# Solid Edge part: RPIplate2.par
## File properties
Author: wojci
Template: ISO Metric Part.par
Last saved by: wojci
Revision: 7
Application: Solid Edge
Username: wojci
Accuracy: 0.990
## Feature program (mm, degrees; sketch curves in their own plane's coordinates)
sketch for "unnamed Protrusion 1" plane through (0, 0, 0) normal (0, 0, 1) x-axis (1, 0, 0)
  line (29, -49) -> (-29, -49)
  line (-29, -49) -> (-29, 47)
  line (-29, 47) -> (29, 47)
  line (29, 47) -> (29, -49)
extrude "unnamed Protrusion 1" add finite 3 along +normal
sketch for "ExtrudedProtrusion_2" plane through (0, -1, 0) normal (0, 0, -1) x-axis (1, 0, 0)
  line (-26, -17) -> (-26, 42)
  line (-26, 42) -> (42, 42)
  line (42, 42) -> (42, -17)
  line (42, -17) -> (-26, -17)
extrude "ExtrudedProtrusion_2" add finite 3 along -normal
sketch for "ExtrudedProtrusion_3" #1 plane through (-3, -1, 3) normal (0, 0, 1) x-axis (0, 1, 0)
  line (-38.5, -41.5) -> (-38.5, 19.5)
  line (-38.5, 19.5) -> (13.5, 19.5)
  line (13.5, 19.5) -> (13.5, -41.5)
  line (13.5, -41.5) -> (-38.5, -41.5)
sketch for "ExtrudedProtrusion_3" #2 plane through (-3, -1, 3) normal (0, 0, 1) x-axis (0, 1, 0)
  line (-35.5, -38.5) -> (-35.5, 16.5)
  line (-35.5, 16.5) -> (10.5, 16.5)
  line (10.5, 16.5) -> (10.5, -38.5)
  line (10.5, -38.5) -> (-35.5, -38.5)
extrude "ExtrudedProtrusion_3" add finite 11 along +normal
sketch for "ExtrudedProtrusion_4" #1 plane through (3, -9.5, 3) normal (0, 0, 1) x-axis (-1, 0, 0)
  circle centre (-34, 28.5) radius 4
sketch for "ExtrudedProtrusion_4" #2 plane through (3, -9.5, 3) normal (0, 0, 1) x-axis (-1, 0, 0)
  circle centre (-34, -20.5) radius 4
sketch for "ExtrudedProtrusion_4" #3 plane through (3, -9.5, 3) normal (0, 0, 1) x-axis (-1, 0, 0)
  circle centre (24, -20.5) radius 4
sketch for "ExtrudedProtrusion_4" #4 plane through (3, -9.5, 3) normal (0, 0, 1) x-axis (-1, 0, 0)
  circle centre (24, 28.5) radius 4
extrude "ExtrudedProtrusion_4" add finite 14 along +normal
sketch for "Hole_1" plane through (4.75, -1, 3) normal (0, 0, 1) x-axis (-1, 0, 0)
hole "Hole_1" diameter 3.6 through
sketch for "unnamed Hole 1" plane through (4.75, -1, 3) normal (0, 0, 1) x-axis (-1, 0, 0)
  hole centre (21.75, -41) bore radius 1.8
hole "unnamed Hole 1" through
sketch for "unnamed Hole 2" plane through (4.75, -1, 3) normal (0, 0, 1) x-axis (-1, 0, 0)
  hole centre (4.75, -1) bore radius 1.8
hole "unnamed Hole 2" through
sketch for "unnamed Hole 3" plane through (4.75, -1, 3) normal (0, 0, 1) x-axis (-1, 0, 0)
  hole centre (-2.25, 47) bore radius 1.8
hole "unnamed Hole 3" through
sketch for "unnamed Hole 4" plane through (4.75, -1, 3) normal (0, 0, 1) x-axis (-1, 0, 0)
  hole centre (11.75, 47) bore radius 1.8
hole "unnamed Hole 4" through
sketch for "Hole_6" plane through (-26, 15, 17) normal (0, 0, 1) x-axis (1, 0, 0)
  hole centre (5, -4) bore radius 1.0065
hole "Hole_6" nominal diameter 2.5 through  ThreadDepth = 6.2 mm
sketch for "unnamed Hole 5" plane through (-26, 15, 17) normal (0, 0, 1) x-axis (1, 0, 0)
  hole centre (5, -53) bore radius 1.0065
hole "unnamed Hole 5" through
sketch for "unnamed Hole 6" plane through (-26, 15, 17) normal (0, 0, 1) x-axis (1, 0, 0)
  hole centre (63, -53) bore radius 1.0065
hole "unnamed Hole 6" through
sketch for "unnamed Hole 7" plane through (-26, 15, 17) normal (0, 0, 1) x-axis (1, 0, 0)
  hole centre (63, -4) bore radius 1.0065
hole "unnamed Hole 7" through
sketch for "unnamed Cutout 1" plane through (6.5, -1, 3) normal (0, 0, 1) x-axis (-1, 0, 0)
  line (-18.5, -8.5) -> (-18.5, -35.5)
  line (-18.5, -35.5) -> (18.5, -35.5)
  line (18.5, -35.5) -> (18.5, -8.5)
  line (18.5, -8.5) -> (-18.5, -8.5)
extrude "unnamed Cutout 1" cut through along +normal
sketch for "ExtrudedProtrusion_17" plane through (6.5, -1, 3) normal (0, 0, 1) x-axis (-1, 0, 0)
  line (18.5, -35.5) -> (18.5, -8.5)
  line (18.5, -8.5) -> (-18.5, -8.5)
  line (-18.5, -8.5) -> (-18.5, -35.5)
  line (-18.5, -35.5) -> (18.5, -35.5)
extrude "ExtrudedProtrusion_17" add finite 8 along +normal
sketch for "ExtrudedCutout_10" plane through (25, 23.5, 7) normal (1, 0, 0) x-axis (0, 1, 0)
  line (11, -3) -> (-15.3249, 3)
  line (-16, 3) -> (-15.3249, 3)
  line (-16, 4) -> (-16, 3)
  line (11, 4) -> (-16, 4)
  line (11, -3) -> (11, 4)
  dimension (linear) = 11
extrude "ExtrudedCutout_10" cut finite 37 along -normal
sketch for "ExtrudedCutout_11" plane through (6.5, 0.9698, 11.6423) normal (0, 0.222222, 0.974996) x-axis (-1, 0, 0)
  line (15, -30.8901) -> (15, -10.8901)
  circle centre (15, -10.8901) radius 3
  line (15, -10.8901) -> (-15, -10.8901)
  circle centre (-15, -10.8901) radius 3
  line (-15, -10.8901) -> (-15, -30.8901)
  circle centre (-15, -30.8901) radius 3
  line (-15, -30.8901) -> (15, -30.8901)
  circle centre (15, -30.8901) radius 3
extrude "ExtrudedCutout_11" cut finite 2 along -normal
sketch for "ExtrudedCutout_12" #1 plane through (6.5, 0.9698, 11.6423) normal (0, 0.222222, 0.974996) x-axis (-1, 0, 0)
  line (0, 0) -> (0, 0)
  line (-18.5, -34.3901) -> (-18.5, -7.3901)
  line (-18.5, -7.3901) -> (18.5, -7.3901)
  line (18.5, -7.3901) -> (18.5, -34.3901)
  line (18.5, -34.3901) -> (-18.5, -34.3901)
sketch for "ExtrudedCutout_12" #2 plane through (6.5, 0.9698, 11.6423) normal (0, 0.222222, 0.974996) x-axis (-1, 0, 0)
  line (-15, -10.8901) -> (-15, -30.8901)
  circle centre (-15, -30.8901) radius 3
  line (-15, -30.8901) -> (15, -30.8901)
  circle centre (15, -30.8901) radius 3
  line (15, -30.8901) -> (15, -10.8901)
  circle centre (15, -10.8901) radius 3
  line (15, -10.8901) -> (-15, -10.8901)
  circle centre (-15, -10.8901) radius 3
extrude "ExtrudedCutout_12" cut finite 18 along -normal
sketch for "ExtrudedCutout_13" plane through (6.5, 7.8376, 10) normal (0, 0, 1) x-axis (-1, 0, 0)
  line (-18.5, 0.3376) -> (18.5, 0.3376)
  line (18.5, 0.3376) -> (18.5, -0.3376)
  line (18.5, -0.3376) -> (-18.5, -0.3376)
  line (-18.5, -0.3376) -> (-18.5, 0.3376)
extrude "ExtrudedCutout_13" cut finite 4 along -normal
sketch for "ExtrudedProtrusion_19" #1 plane through (6.5, 0.9698, 11.6423) normal (0, 0.222222, 0.974996) x-axis (-1, 0, 0)
  circle centre (-15, -10.8901) radius 3
sketch for "ExtrudedProtrusion_19" #2 plane through (6.5, 0.9698, 11.6423) normal (0, 0.222222, 0.974996) x-axis (-1, 0, 0)
  circle centre (15, -10.8901) radius 3
extrude "ExtrudedProtrusion_19" add finite 8 along -normal
sketch for "ExtrudedProtrusion_20" plane through (6.5, 19.7421, 0) normal (0, 0, -1) x-axis (0, 1, 0)
  line (-13.8462, 18.5) -> (14.7579, 18.5)
  line (14.7579, 18.5) -> (14.7579, -18.5)
  line (14.7579, -18.5) -> (-13.8462, -18.5)
  line (-13.8462, -18.5) -> (-13.8462, 18.5)
extrude "ExtrudedProtrusion_20" add finite 3 along -normal
sketch for "Hole_16" plane through (21.5, 31.0875, 4.7778) normal (0, 0.222222, 0.974996) x-axis (-1, 0, 0)
  hole centre (0, 0) bore radius 1.2295
hole "Hole_16" nominal diameter 3 through  ThreadDepth = 2 mm
sketch for "unnamed Hole 8" plane through (21.5, 31.0875, 4.7778) normal (0, 0.222222, 0.974996) x-axis (-1, 0, 0)
  hole centre (0, 20) bore radius 1.2295
hole "unnamed Hole 8" through
sketch for "unnamed Hole 9" plane through (21.5, 31.0875, 4.7778) normal (0, 0.222222, 0.974996) x-axis (-1, 0, 0)
  hole centre (30, 20) bore radius 1.2295
hole "unnamed Hole 9" through
sketch for "unnamed Hole 10" plane through (21.5, 31.0875, 4.7778) normal (0, 0.222222, 0.974996) x-axis (-1, 0, 0)
  hole centre (30, 0) bore radius 1.2295
hole "unnamed Hole 10" through
pattern "unnamed Pattern 1" of "Hole_16", "unnamed Hole 8", "unnamed Hole 9", "unnamed Hole 10"
sketch for "ExtrudedProtrusion_21" #1 plane through (6.5, -1, 3) normal (0, 0, 1) x-axis (-1, 0, 0)
  line (-18.5, -10.5) -> (-16.9587, -10.5)
  line (-16.9587, -10.5) -> (-16.9587, -13.5)
  line (-16.9587, -13.5) -> (-18.5, -13.5)
  line (-18.5, -13.5) -> (-18.5, -10.5)
sketch for "ExtrudedProtrusion_21" #2 plane through (6.5, -1, 3) normal (0, 0, 1) x-axis (-1, 0, 0)
  line (18.5, -10.5) -> (16.9587, -10.5)
  line (16.9587, -10.5) -> (16.9587, -13.5)
  line (16.9587, -13.5) -> (18.5, -13.5)
  line (18.5, -13.5) -> (18.5, -10.5)
extrude "ExtrudedProtrusion_21" add finite 5 along +normal
chamfer "Chamfer_3" setback 6.5
sketch for "unnamed Cutout 2" plane through (25, 34.386, 3.5) normal (1, 0, 0) x-axis (0, 1, 0)
  line (0.114, 0.5) -> (-0.114, 0.5)
  line (-0.114, 0.5) -> (-0.114, -0.5)
  line (-0.114, -0.5) -> (0.114, -0.5)
  line (0.114, -0.5) -> (0.114, 0.5)
extrude "unnamed Cutout 2" cut through along -normal
sketch for "unnamed Cutout 3" plane through (8, -39.5, 8.5) normal (0, -1, 0) x-axis (1, 0, 0)
  line (5.2919, 5.5) -> (7.1675, -1.5)
  line (7.1675, -1.5) -> (18.4163, -1.5)
  line (20.2919, 5.5) -> (18.4163, -1.5)
  line (5.2919, 5.5) -> (20.2919, 5.5)
extrude "unnamed Cutout 3" cut through along -normal
sketch used by "ExtrudedProtrusion_22" plane through (6.5, -1, 3) normal (0, 0, 1) x-axis (0, 1, 0)
extrude "ExtrudedProtrusion_22" add finite 16 along +normal
sketch for "ExtrudedCutout_16" #1 plane through (41, -13.5, 19) normal (0, 0, 1) x-axis (0, 1, 0)
sketch for "ExtrudedCutout_16" #2 plane through (41, -13.5, 19) normal (0, 0, 1) x-axis (0, 1, 0)
extrude "ExtrudedCutout_16" cut finite 5 along -normal
sketch for "unnamed Cutout 4" plane through (40.25, -13.5, 14) normal (0, 0, 1) x-axis (0, 1, 0)
extrude "unnamed Cutout 4" cut through along -normal
fillet "Round_11" radius 5.5
chamfer "Chamfer_4" setback 2.925
fillet "Round_12" radius 4
fillet "Round_13" radius 3
fillet "Round_15" radius 5.75
fillet "Round_16" radius 1
fillet "Round_17" radius 2.5
pattern "unnamed Pattern 2" of "Hole_1", "unnamed Hole 1", "unnamed Hole 2", "unnamed Hole 3", "unnamed Hole 4"
pattern "unnamed Pattern 3" of "Hole_6", "unnamed Hole 5", "unnamed Hole 6", "unnamed Hole 7"
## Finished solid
Body 1: solid body, 123 faces, 309 edges, 178 vertices.
  Faces by surface: plane 66, cylinder 53, blend 2, torus 2
  Edges by curve: line 176, circle 107, ellipse 21, intersection 4, curve on surface 1
Bounding box of the edges (mm; curved faces can reach further): 74.000 x 96.000 x 19.000, from (-29, -49, 0) to (45, 47, 19).
Cylindrical faces by radius (mm): R1 x2, R1.0065 x8, R1.2295 x8, R1.8 x5, R2.5 x9, R3 x6, R4 x6, R5.5 x1, R5.75 x8
Toroidal faces (ring radius, tube radius in mm): R6.5 r1 x2
Planar faces by outward normal: +x 10, +y 7, +z 19, -x 6, -y 9, -z 3, oblique 12
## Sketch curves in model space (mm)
line (29, 34.5, 3) -> (-29, 34.5, 3)
line (-12, 34.5, 3) -> (-12, 7.5, 3)
line (-12, 7.5, 3) -> (25, 7.5, 3)
line (25, 7.5, 3) -> (25, 34.5, 3)
line (25, 34.5, 3) -> (-12, 34.5, 3)
line (37, -3.5, 3) -> (45, -3.5, 3)
line (45, -3.5, 3) -> (45, -23.5, 3)
line (45, -23.5, 3) -> (37, -23.5, 3)
line (37, -23.5, 3) -> (37, -3.5, 3)
line (-29, -43, 0) -> (29, -43, 0)
line (37, 11, 0) -> (-21, 11, 0)
line (-21, 11, 0) -> (-21, -38, 0)
line (-21, -38, 0) -> (37, -38, 0)
line (37, -38, 0) -> (37, 11, 0)
line (42, 16, 0) -> (-26, 16, 0)
line (-26, 16, 0) -> (-26, -43, 0)
line (-26, -43, 0) -> (42, -43, 0)
line (42, -43, 0) -> (42, 16, 0)
circle centre (21.5, 11.5876, 9.2222) radius 3
circle centre (-8.5, 11.5876, 9.2222) radius 3
circle centre (-8.5, 31.0875, 4.7778) radius 3
circle centre (21.5, 31.0875, 4.7778) radius 3
line (25, 15.4876, 8.3333) -> (25, 27.1875, 5.6667)
line (-7, 15.4876, 8.3333) -> (25, 15.4876, 8.3333)
line (-7, 27.1875, 5.6667) -> (-7, 15.4876, 8.3333)
line (25, 27.1875, 5.6667) -> (-7, 27.1875, 5.6667)
line (-12, 8.1751, 10) -> (-12, 34.5, 4)
line (-12, 34.5, 4) -> (25, 34.5, 4)
line (25, 34.5, 4) -> (25, 8.1751, 10)
line (25, 8.1751, 10) -> (-12, 8.1751, 10)
line (21.5, 31.0875, 4.7778) -> (-8.5, 31.0875, 4.7778)
line (-8.5, 31.0875, 4.7778) -> (-8.5, 11.5876, 9.2222)
line (-8.5, 11.5876, 9.2222) -> (21.5, 11.5876, 9.2222)
line (21.5, 11.5876, 9.2222) -> (21.5, 31.0875, 4.7778)
line (25, 21.3376, 7) -> (-12, 21.3376, 7)
line (6.5, 34.5, 4) -> (6.5, 8.1751, 10)
line (-29, -48, 0) -> (29, -48, 0)
line (-29, 40, 0) -> (29, 40, 0)
line (-29, 0, 0) -> (29, 0, 0)
line (0, 47, 0) -> (0, -49, 0)
line (29, 47, 0) -> (29, -49, 0)
line (29, -49, 0) -> (-29, -49, 0)
line (-29, -49, 0) -> (-29, 47, 0)
line (-29, 47, 0) -> (29, 47, 0)
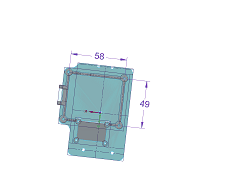
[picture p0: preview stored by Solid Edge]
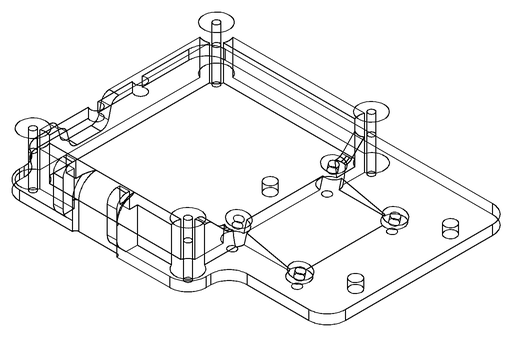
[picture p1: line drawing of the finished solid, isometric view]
